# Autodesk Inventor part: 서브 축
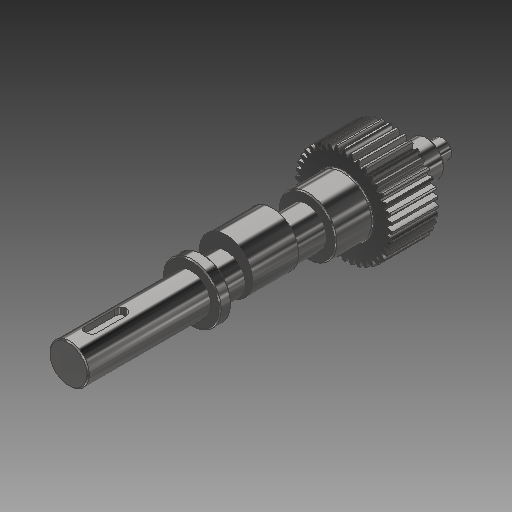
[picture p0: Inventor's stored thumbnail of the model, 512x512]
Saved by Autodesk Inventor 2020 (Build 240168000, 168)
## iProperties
CustomPartVersion: 1
Created: 2016-02
Part Number: 서브 축
Material: 강철, 연강
Document SubType Name: Modeling
Designer: mdu
Categories: <?xml version="1.0" encoding="UTF-16"?> <MemberInstance><Categories><FamilyTemplate><FamilyTemplateParameter ValueType="xs:double" Id="1" ObjectReferenceKey="da
Density: 7.86 g/cm^3
Mass: 506.173 g
Surface Area: 164.116 cm^2
Volume: 64.3986 cm^3
Appearance: 강철 - 광택
Author: mdu
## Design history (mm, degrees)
sketch "Sketch1"
  geometry: C1 r 21 at (0, 0)
  constraints: 1 centre point
  dimensions: "d0" = 42 diameter of C1 (= da_da)
extrude "Extrusion1" new body sketch "Sketch1" distance "d1" = 20 (= da_b); taper "d2" = 0 deg
workplane "Work Plane2"
feature "피치 지름" dims "d4" = 10, "d5" = 0
workplane "Work Plane8"
workplane "Work Plane9"
chamfer "모따기1" distance "d49" = 0.2; stored, may be unused: second distance "d50" = 2, angle "d51" = 45 deg
sketch "스케치3"
  geometry: C1 r 12.5 at (0, 0); 1 further point
  constraints: 1 centre point, 1 coincident
  dimensions: "d52" = 25 diameter of C1
extrude "돌출2" join sketch "스케치3" distance "d53" = 16; taper "d54" = 0 deg
sketch "스케치4"
  geometry: C1 r 8.5 at (0, 0); 1 further point
  constraints: 1 centre point, 1 coincident
  dimensions: "d55" = 17 diameter of C1
extrude "돌출3" join sketch "스케치4" distance "d56" = 103; taper "d57" = 0 deg
sketch "스케치5"
  geometry: C1 r 7.5 at (0, 0); 1 further point
  constraints: 1 centre point, 1 coincident
  dimensions: "d62" = 15 diameter of C1
extrude "돌출4" join sketch "스케치5" distance "d63" = 16; taper "d64" = 0 deg
sketch "스케치6"
  geometry: C1 r 4 at (0, 0); 1 further point
  constraints: 1 centre point, 1 coincident
  dimensions: "d65" = 8 diameter of C1
extrude "돌출5" join sketch "스케치6" distance "d66" = 7; taper "d67" = 0 deg
chamfer "모따기2" distance "d58" = 0.5; stored, may be unused: second distance "d59" = 2, angle "d60" = 45 deg
fillet "모깎기1" dims "d61" = 0.5
feature "스퍼 기어" dims "da_b" = 20, "da_d" = 40, "da_aw" = 31, "da_da" = 42, "da_df" = 37.5, "da_dw" = 40, angle "da_beta" = 0 deg, "da_lefttooth" = 0, "da_righttooth" = 0
node "작업 평면11"
sketch "스케치7"
  geometry: C1 r 8.5 at (0, 0) reference; C2 r 11.5 at (0, 3); 1 further point
  constraints: 1 centre point, 1 tangent, 1 vertical alignment
  dimensions: "d71" = 3 distance of C2.centre point (0, 0); "d72" = 23 diameter of C2 (derived)
extrude "돌출6" join sketch "스케치7" stored distance "d73" = 20; taper "d74" = 0 deg
node "작업 평면12"
sketch "스케치8"
  geometry: C1 r 12.5 at (0, 0) reference; 1 further point
extrude "돌출7" join sketch "스케치8" distance "d76" = 5; taper "d77" = 0 deg
chamfer "모따기3" distance "d78" = 0.5; stored, may be unused: second distance "d79" = 2, angle "d80" = 45 deg
sketch "스케치9"
  geometry: L1 (-8.5, 86)-(-8.5, 138.5) reference; L2 (-8, 139)-(8, 139) reference; L3 (0, 0)-(0, 139); L4 (-8.5, 115)-(0, 115); L5 (-8.5, 115)-(-8.5, 113.5); L6 (-7, 115)-(-8.5, 113.5)
  constraints: 8 end point, 4 point on line, 1 midpoint, 1 perpendicular
  dimensions: "d81" = 24 distance between parallel lines of L2 L4; "d82" = 45 deg angle of L6 L5; "d83" = 3 diameter of L5.end L4
revolve "회전1" sketch "스케치9" stored, may be unused: angle "d84" = 90 deg
sketch "스케치10"
  geometry: L1 (-8.5, 113.5)-(-7, 115) reference; L2 (-8.5, 116.5)-(-7, 115) reference; 2 further points
  constraints: 1 coincident
node "작업점1"
node "작업 평면14"
sketch "스케치11"
  geometry: L1 (8.5, 102.5)-(-8.5, 102.5) reference; L2 (0, 102.5)-(0, -36); L3 (-2.5, 93.5)-(-2.5, 80.5); L4 (2.5, 80.5)-(2.5, 93.5); L5 (-8, 103)-(8, 103) reference; A1 r 2.5 centre (0, 93.5) between (2.5, 93.5) and (-2.5, 93.5); A2 r 2.5 centre (0, 80.5) between (-2.5, 80.5) and (2.5, 80.5)
  constraints: 6 end point, 4 point on circle, 4 tangent, 2 centre point, 1 midpoint, 1 parallel, 1 perpendicular, 1 point on line, 1 vertical alignment
  dimensions: "d85" = 7 distance edge to line of A1 L5; "d86" = 18 dimension on A2 A1; "d87" = 5 distance between parallel lines of L3 L4
extrude "돌출8" cut sketch "스케치11" distance "d88" = 3; taper "d89" = 0 deg
body "Solid1"
sketch "Sketch2"
  geometry: C1 r 21 at (0, 0) reference; C2 r 20 at (0, 0)
  constraints: 1 centre point, 1 coincident
  dimensions: "d3" = 40 diameter of C2 (= da_dw)
body "Srf1"
other parameters: "d16" = 31 (= da_aw), "d17" = 0, "d34" = 4.5 deg (computed from da_z), "d39" = 0, "d41" = 0, "d43" = 31 (= da_aw), "d46" = 31 (= da_aw), "d47" = 0, "d48" = 0, "d68" = 25
